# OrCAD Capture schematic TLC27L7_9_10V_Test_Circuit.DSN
size A; title: TLC27L2, TLC27L2A, TLC27L2B, TLC27L7 LinCMOS; rev: 1.1; note: Datasheet: SLOS052D EVM: N/A
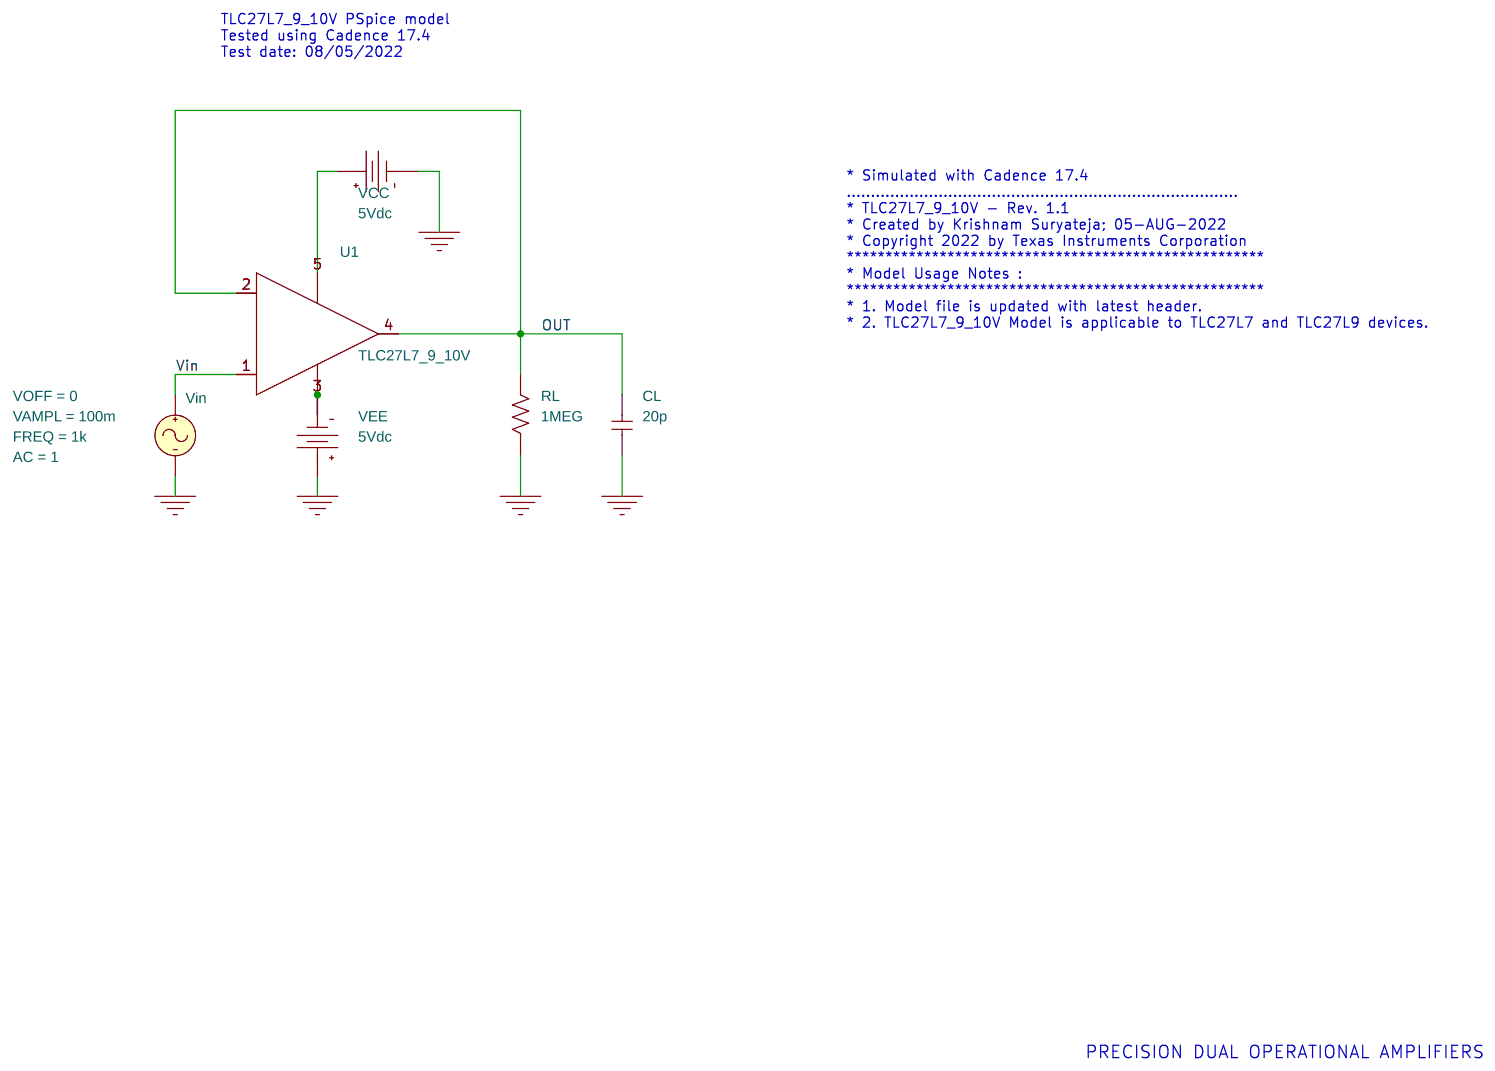
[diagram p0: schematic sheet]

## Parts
CL  20p  [RAD/CK05]
RL  1MEG  [AX/RC05]
U1  TLC27L7_9_10V
VCC  VDC
VEE  VDC
Vin  VSIN

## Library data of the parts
CL = C
RL = R
U1 = TLC27L7_9_10V
VCC VEE = VDC: DC: 5Vdc
Vin = VSIN: AC: 1; FREQ: 1k; VAMPL: 100m; VOFF: 0

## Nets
Vin: U1.1(+) Vin.1(+)
0: CL.1 RL.1 VCC.1(-) VEE.0(+) Vin.2(-)
OUT: CL.2 RL.2 U1.2(-) U1.4(OUT)
N22995: U1.5(V+) VCC.0(+)
N23017: U1.3(V-) VEE.1(-)

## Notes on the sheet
- TLC27L7_9_10V PSpice model
  Tested using Cadence 17.4
  Test date: 08/05/2022
- * Simulated with Cadence 17.4
  .................................................................................
  * TLC27L7_9_10V - Rev. 1.1
  * Created by Krishnam Suryateja; 05-AUG-2022
  * Copyright 2022 by Texas Instruments Corporation
  ******************************************************
  * Model Usage Notes :
  ******************************************************
  * 1. Model file is updated with latest header.
  * 2. TLC27L7_9_10V Model is applicable to TLC27L7 and TLC27L9 devices.
- PRECISION DUAL OPERATIONAL AMPLIFIERS
